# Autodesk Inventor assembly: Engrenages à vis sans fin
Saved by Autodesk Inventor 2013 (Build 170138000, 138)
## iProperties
Created: 2011-07
Part Number: Engrenages à vis sans fin
Document SubType Name: Assembly
Designer: Laur
ClientObjectVersion: 1
Author: Laur
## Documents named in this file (2)
- D:\_an13-14\FORMULAIRE_2014\Sujet E4 Poissy 2014\Modélisation_7970_shimano_2014\vis sans fin arbrée\Design Accelerator\Engrenages à vis sans fin1.iam
- D:\_an13-14\FORMULAIRE_2014\Sujet E4 Poissy 2014\Modélisation_7970_shimano_2014\vis sans fin arbrée\Design Accelerator\Vis sans fin2.ipt
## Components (1 placed, 1 different names)
1. Vis sans fin:1
